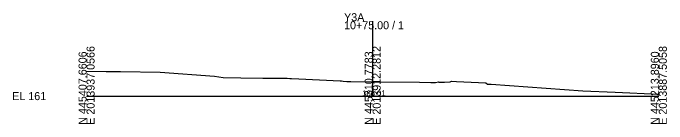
# Model space of a CAD drawing. Extents: x -26 to 205, y -10 to 5029.
# Drawn here: x -25.7 to 202.8, y 1490.3 to 1529 of the extents above; entities that cross this region are included whole.
import ezdxf

# ---------------------------------------------------------------- set-up
doc = ezdxf.new("R2010")
doc.units = 0
for name, color, linetype in [('Default', 7, 'Continuous'), ('Exist Cross Section Cell', 7, 'Continuous'), ('Exist XS Center Line Elevation Label', 7, 'Continuous'), ('Exist XS Ground Line', 7, 'Continuous')]:
    doc.layers.add(name, color=color, linetype=linetype)

msp = doc.modelspace()

# ---------------------------------------------------------------- linework, layer by layer
at = {"layer": 'Exist Cross Section Cell'}
for p, q in [((100, 1500), (100, 1526.13)), ((0, 1500), (100, 1500)), ((100, 1500), (200, 1500))]:
    msp.add_line(p, q, dxfattribs=at)
at = {"layer": 'Exist XS Ground Line'}
msp.add_lwpolyline([(0, 1508.71), (6.89, 1508.62), (11.91, 1508.58), (25.68, 1508.4), (44.73, 1507.01), (47.72, 1506.52), (53.93, 1506.43), (61.6, 1506.28), (70.11, 1506.21), (71.08, 1506.19), (71.66, 1506.17), (74.18, 1506.04), (88.63, 1505.37), (89.08, 1505.35), (89.64, 1505.27), (90.91, 1505.11), (91.26, 1505.05), (92.38, 1505.05), (100, 1505.01), (102.74, 1505), (116.32, 1504.83), (120.37, 1504.76), (120.68, 1504.76), (122.01, 1504.75), (123.04, 1505.01), (123.08, 1504.84), (125.14, 1504.88), (127.1, 1504.94), (127.5, 1505.2), (129.26, 1505.12), (139.57, 1504.61), (140.12, 1504.15), (141.44, 1504.13), (173.44, 1501.8), (184.76, 1501.33), (200, 1500.71)], dxfattribs=at)

# ---------------------------------------------------------------- texts
at = {"layer": 'Default'}
msp.add_text('-', height=0.0001, dxfattribs=at).set_placement((0, 1500))
at = {"layer": 'Exist Cross Section Cell'}
for s, p in [('Y3A', (90, 1526.13)), ('10+75.00 / 1', (90, 1523.33)), ('EL 161', (-26, 1498.6))]:
    msp.add_text(s, height=2.8, dxfattribs=at).set_placement(p)
for s, p in [('N 445407.6606', (0, 1490)), ('E 2013937.0566', (2.8, 1490)), ('N 445310.7783', (100, 1490)), ('E 2013912.2812', (102.8, 1490)), ('N 445213.8960', (200, 1490)), ('E 2013887.5058', (202.8, 1490))]:
    msp.add_text(s, height=2.8, rotation=90, dxfattribs=at).set_placement(p)
at = {"layer": 'Exist XS Center Line Elevation Label'}
msp.add_text('166.01', height=2, dxfattribs=at).set_placement((96.32, 1500.01))

doc.saveas('drawing.dxf')
